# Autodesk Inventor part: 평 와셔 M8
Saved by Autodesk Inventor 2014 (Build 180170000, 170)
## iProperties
Created: 2025-10
Part Number: 평 와셔 M8
Material: 일반
Document SubType Name: Modeling
Designer: dg
Density: 1 g/cm^3
Appearance: 기본값
Author: dg
Author: jhkim
Description: 평면 와셔
Creation Date: 2025-10-01
Sending System: Autodesk Inventor 2026
Preprocessor: ST-DEVELOPER v20.1
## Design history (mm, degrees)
node "평 와셔 M81"
body "Solid1"
node "기준1"
